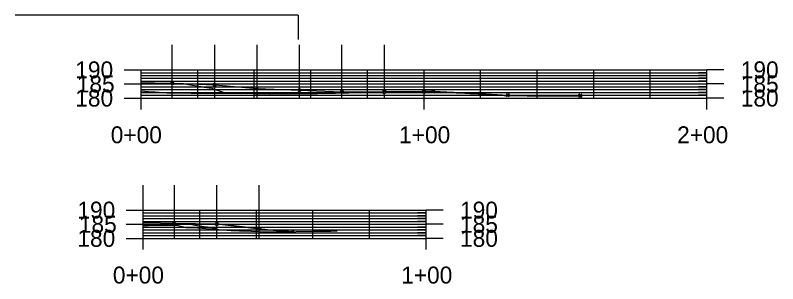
# Model space of a CAD drawing. Extents: x 1 to 1477871, y 1 to 1872901.
# Drawn here: x 1446288.5 to 1446558.1, y 1852258.5 to 1852353.6 of the extents above; entities that cross this region are included whole.
import ezdxf

# ---------------------------------------------------------------- set-up
doc = ezdxf.new("R2010")
doc.units = 0
for name, color, linetype in [('B_Concrete', 7, 'Continuous'), ('Default', 7, 'Continuous'), ('R_Axis', 7, 'Continuous'), ('R_Axis Annot', 7, 'Continuous'), ('R_Grid', 7, 'Continuous'), ('R_No Plot', 7, 'Continuous'), ('R_Point Sym', 7, 'Continuous'), ('R_Vert Alg Annot', 7, 'Continuous')]:
    doc.layers.add(name, color=color, linetype=linetype)

msp = doc.modelspace()

# ---------------------------------------------------------------- linework, layer by layer
at = {"layer": 'B_Concrete'}
msp.add_line((1446488.3, 1852324.99), (1446488.3, 1852325.56), dxfattribs=at)
at = {"layer": 'Default'}
for p, q in [((1446344.04, 1852329.55), (1446359.04, 1852328.95)), ((1446344.04, 1852329.55), (1446359.04, 1852328.95)), ((1446359.04, 1852328.95), (1446374.04, 1852327.66)), ((1446359.04, 1852328.95), (1446374.04, 1852327.66)), ((1446374.04, 1852327.66), (1446389.04, 1852327.06)), ((1446374.04, 1852327.66), (1446389.04, 1852327.06)), ((1446389.04, 1852327.06), (1446404.04, 1852326.46)), ((1446389.04, 1852327.06), (1446404.04, 1852326.46)), ((1446404.04, 1852326.46), (1446419.04, 1852326.59)), ((1446404.04, 1852326.46), (1446419.04, 1852326.41)), ((1446419.04, 1852326.59), (1446433.04, 1852326.69)), ((1446419.04, 1852326.41), (1446433.04, 1852326.54)), ((1446433.04, 1852326.69), (1446436.35, 1852326.69)), ((1446433.04, 1852326.54), (1446436.33, 1852326.57)), ((1446436.33, 1852326.57), (1446453.04, 1852325.73)), ((1446436.35, 1852326.69), (1446453.04, 1852325.87)), ((1446453.04, 1852325.87), (1446462.75, 1852325.35)), ((1446453.04, 1852325.73), (1446462.7, 1852325.18)), ((1446462.7, 1852325.18), (1446488.3, 1852324.99)), ((1446462.75, 1852325.35), (1446488.3, 1852325.21)), ((1446344.78, 1852279.98), (1446359.78, 1852279.69)), ((1446359.78, 1852279.69), (1446374.78, 1852277.96)), ((1446374.78, 1852277.96), (1446386.68, 1852276.99))]:
    msp.add_line(p, q, dxfattribs=at)
for points in [[(1446333.04, 1852329.77), (1446333.04, 1852329.77), (1446342.55, 1852329.57), (1446344.04, 1852329.55), (1446347.47, 1852329.41), (1446348.04, 1852329.39), (1446349.07, 1852329.21), (1446354.88, 1852328.24), (1446355.34, 1852328.17), (1446358.04, 1852327.72), (1446358.8, 1852327.46), (1446363.15, 1852326.01)], [(1446333.04, 1852329.77), (1446333.04, 1852329.77), (1446342.55, 1852329.57), (1446344.04, 1852329.55), (1446347.47, 1852329.41), (1446348.04, 1852329.39), (1446349.07, 1852329.21), (1446354.88, 1852328.24), (1446355.34, 1852328.17), (1446358.04, 1852327.72), (1446358.8, 1852327.46), (1446363.15, 1852326.01)], [(1446333.04, 1852326.8), (1446335.68, 1852326.62), (1446337.98, 1852326.44), (1446342.15, 1852326.08), (1446345.2, 1852326.07), (1446350.71, 1852326.01), (1446355.72, 1852325.97), (1446359, 1852326), (1446361.44, 1852326.01), (1446363.73, 1852326.02), (1446365.32, 1852326.02), (1446366.9, 1852326.03), (1446368.31, 1852326.03), (1446368.48, 1852326.03), (1446370.07, 1852325.99), (1446371.65, 1852325.96), (1446373.24, 1852325.92), (1446374.39, 1852325.9), (1446374.82, 1852325.89), (1446375.37, 1852325.88), (1446376.41, 1852325.86), (1446377.99, 1852325.83), (1446378.39, 1852325.82), (1446379.58, 1852325.83), (1446381.16, 1852325.84), (1446382.74, 1852325.85), (1446383.12, 1852325.85), (1446384.33, 1852325.85), (1446385.91, 1852325.85), (1446386.93, 1852325.85), (1446387.5, 1852325.86), (1446389.08, 1852325.88), (1446390.67, 1852325.9), (1446390.75, 1852325.9), (1446392.25, 1852325.9), (1446393.84, 1852325.9), (1446394.57, 1852325.9), (1446395.42, 1852325.92), (1446396.5, 1852325.95), (1446397, 1852325.96), (1446398.59, 1852325.99), (1446400.17, 1852326.02), (1446401.14, 1852326.04), (1446401.76, 1852326.05), (1446403.34, 1852326.09), (1446404.93, 1852326.13), (1446406.51, 1852326.17), (1446408.1, 1852326.21), (1446409.68, 1852326.25), (1446411.27, 1852326.29), (1446411.54, 1852326.3), (1446412.85, 1852326.31), (1446414.43, 1852326.33), (1446415.19, 1852326.34), (1446416.02, 1852326.36), (1446417.6, 1852326.39), (1446419.19, 1852326.41), (1446420.77, 1852326.44), (1446421.96, 1852326.46), (1446422.36, 1852326.46), (1446423.82, 1852326.44), (1446423.94, 1852326.44), (1446425.53, 1852326.49), (1446425.96, 1852326.5), (1446427.11, 1852326.5), (1446428.68, 1852326.52), (1446430.25, 1852326.53), (1446431.82, 1852326.54), (1446431.82, 1852326.54), (1446433.39, 1852326.54), (1446434.96, 1852326.55), (1446436.33, 1852326.55), (1446436.52, 1852326.54), (1446438.09, 1852326.46), (1446439.66, 1852326.38), (1446440.62, 1852326.33), (1446441.23, 1852326.3), (1446442.8, 1852326.23), (1446444.37, 1852326.16), (1446445.49, 1852326.11), (1446445.94, 1852326.09), (1446447.51, 1852326.02), (1446449.08, 1852325.95), (1446449.21, 1852325.94), (1446450.65, 1852325.86), (1446452.22, 1852325.78), (1446452.58, 1852325.77), (1446453.78, 1852325.68), (1446455.35, 1852325.58), (1446456.92, 1852325.48), (1446458.49, 1852325.38), (1446460.06, 1852325.3), (1446461.34, 1852325.23), (1446461.63, 1852325.21), (1446462.69, 1852325.13), (1446463.2, 1852325.13), (1446464.77, 1852325.13), (1446466.34, 1852325.12), (1446467.91, 1852325.12), (1446469.48, 1852325.11), (1446469.93, 1852325.11), (1446471.04, 1852325.1), (1446472.61, 1852325.1), (1446474.18, 1852325.09), (1446475.75, 1852325.08), (1446477.32, 1852325.07), (1446477.36, 1852325.07), (1446478.89, 1852325.06), (1446479.37, 1852325.06), (1446480.46, 1852325.06), (1446481.94, 1852325.05), (1446482.03, 1852325.05), (1446483.6, 1852325.03), (1446485.17, 1852325.02), (1446486.74, 1852325.01), (1446488.3, 1852324.99)], [(1446333.04, 1852326.8), (1446335.68, 1852326.62), (1446337.98, 1852326.44), (1446342.15, 1852326.08), (1446345.2, 1852326.07), (1446350.71, 1852326.01), (1446355.72, 1852325.97), (1446359, 1852326), (1446361.44, 1852326.01), (1446363.73, 1852326.02), (1446365.32, 1852326.02), (1446366.9, 1852326.03), (1446368.31, 1852326.03), (1446368.48, 1852326.03), (1446370.07, 1852325.99), (1446371.65, 1852325.96), (1446373.24, 1852325.92), (1446374.39, 1852325.9), (1446374.82, 1852325.89), (1446375.37, 1852325.88), (1446376.41, 1852325.86), (1446377.99, 1852325.83), (1446378.39, 1852325.82), (1446379.58, 1852325.83), (1446381.16, 1852325.84), (1446382.74, 1852325.85), (1446383.12, 1852325.85), (1446384.33, 1852325.85), (1446385.91, 1852325.85), (1446386.93, 1852325.85), (1446387.5, 1852325.86), (1446389.08, 1852325.88), (1446390.67, 1852325.9), (1446390.75, 1852325.9), (1446392.25, 1852325.9), (1446393.84, 1852325.9), (1446394.57, 1852325.9), (1446395.42, 1852325.92), (1446396.5, 1852325.95), (1446397, 1852325.96), (1446398.59, 1852325.99), (1446400.17, 1852326.02), (1446401.14, 1852326.04), (1446401.76, 1852326.05), (1446403.34, 1852326.09), (1446404.93, 1852326.13), (1446406.51, 1852326.17), (1446408.1, 1852326.21), (1446409.68, 1852326.25), (1446411.27, 1852326.29), (1446411.54, 1852326.3), (1446412.85, 1852326.31), (1446414.43, 1852326.33), (1446415.19, 1852326.34), (1446416.02, 1852326.36), (1446417.6, 1852326.39), (1446419.19, 1852326.41), (1446420.77, 1852326.44), (1446421.96, 1852326.46), (1446422.36, 1852326.46), (1446423.82, 1852326.44), (1446423.94, 1852326.44), (1446425.53, 1852326.49), (1446425.96, 1852326.5), (1446427.11, 1852326.5), (1446428.68, 1852326.52), (1446430.25, 1852326.53), (1446431.82, 1852326.54), (1446431.82, 1852326.54), (1446433.39, 1852326.54), (1446434.96, 1852326.55), (1446436.33, 1852326.55), (1446436.52, 1852326.54), (1446438.09, 1852326.46), (1446439.66, 1852326.38), (1446440.62, 1852326.33), (1446441.23, 1852326.3), (1446442.8, 1852326.23), (1446444.37, 1852326.16), (1446445.49, 1852326.11), (1446445.94, 1852326.09), (1446447.51, 1852326.02), (1446449.08, 1852325.95), (1446449.21, 1852325.94), (1446450.65, 1852325.86), (1446452.22, 1852325.78), (1446452.58, 1852325.77), (1446453.78, 1852325.68), (1446455.35, 1852325.58), (1446456.92, 1852325.48), (1446458.49, 1852325.38), (1446460.06, 1852325.3), (1446461.34, 1852325.23), (1446461.63, 1852325.21), (1446462.69, 1852325.13), (1446463.2, 1852325.13), (1446464.77, 1852325.13), (1446466.34, 1852325.12), (1446467.91, 1852325.12), (1446469.48, 1852325.11), (1446469.93, 1852325.11), (1446471.04, 1852325.1), (1446472.61, 1852325.1), (1446474.18, 1852325.09), (1446475.75, 1852325.08), (1446477.32, 1852325.07), (1446477.36, 1852325.07), (1446478.89, 1852325.06), (1446479.37, 1852325.06), (1446480.46, 1852325.06), (1446481.94, 1852325.05), (1446482.03, 1852325.05), (1446483.6, 1852325.03), (1446485.17, 1852325.02), (1446486.74, 1852325.01), (1446488.3, 1852324.99)], [(1446333.78, 1852280.19), (1446334.93, 1852280.17), (1446344.78, 1852279.98), (1446345.2, 1852279.97), (1446348.78, 1852279.9), (1446349.55, 1852279.77), (1446352.95, 1852279.2), (1446354.44, 1852278.96), (1446355.92, 1852278.71), (1446356.18, 1852278.66), (1446356.53, 1852278.61), (1446357.41, 1852278.46), (1446358.79, 1852278.23), (1446358.89, 1852278.2), (1446359.07, 1852278.14), (1446360.33, 1852277.73)], [(1446333.78, 1852279.13), (1446335.46, 1852279.19), (1446338.51, 1852279.26), (1446341.85, 1852279.29), (1446344.93, 1852279.25), (1446345.69, 1852279.24), (1446347.55, 1852278.79), (1446348.89, 1852278.46), (1446350.04, 1852278.39), (1446352.95, 1852278.28), (1446353.21, 1852278.28), (1446354.44, 1852278.19), (1446355.92, 1852278.09), (1446357.33, 1852278), (1446357.41, 1852277.99), (1446358.89, 1852277.86), (1446360.37, 1852277.72), (1446361.86, 1852277.59), (1446363.34, 1852277.46), (1446363.38, 1852277.46), (1446364.83, 1852277.4), (1446366.31, 1852277.34), (1446367.8, 1852277.28), (1446369.28, 1852277.22), (1446372.03, 1852277.11), (1446377.09, 1852276.87), (1446379.27, 1852276.88), (1446381.95, 1852276.9), (1446393.63, 1852277.11), (1446396.95, 1852277.17), (1446400.1, 1852277.18), (1446402.29, 1852277.2)]]:
    msp.add_lwpolyline(points, dxfattribs=at)
at = {"layer": 'R_Axis'}
for p, q in [((1446333.04, 1852324.26), (1446333.04, 1852334.26)), ((1446333.04, 1852324.26), (1446333.04, 1852334.26)), ((1446533.04, 1852324.26), (1446533.04, 1852334.26)), ((1446533.04, 1852324.26), (1446533.04, 1852334.26)), ((1446333.04, 1852324.26), (1446533.04, 1852324.26)), ((1446333.04, 1852324.26), (1446533.04, 1852324.26)), ((1446333.78, 1852274.59), (1446333.78, 1852284.59)), ((1446433.78, 1852274.59), (1446433.78, 1852284.59)), ((1446333.78, 1852274.59), (1446433.78, 1852274.59))]:
    msp.add_line(p, q, dxfattribs=at)
at = {"layer": 'R_Grid'}
for p, q in [((1446327.04, 1852334.26), (1446333.04, 1852334.26)), ((1446327.04, 1852334.26), (1446333.04, 1852334.26)), ((1446327.04, 1852334.26), (1446333.04, 1852334.26)), ((1446327.04, 1852334.26), (1446333.04, 1852334.26)), ((1446333.04, 1852334.26), (1446533.04, 1852334.26)), ((1446333.04, 1852334.26), (1446533.04, 1852334.26)), ((1446333.04, 1852334.26), (1446533.04, 1852334.26)), ((1446333.04, 1852334.26), (1446533.04, 1852334.26)), ((1446333.04, 1852333.26), (1446336.04, 1852333.26)), ((1446333.04, 1852333.26), (1446533.04, 1852333.26)), ((1446333.04, 1852333.26), (1446336.04, 1852333.26)), ((1446333.04, 1852333.26), (1446533.04, 1852333.26)), ((1446353.04, 1852324.26), (1446353.04, 1852334.26)), ((1446353.04, 1852324.26), (1446353.04, 1852334.26)), ((1446373.04, 1852324.26), (1446373.04, 1852334.26)), ((1446373.04, 1852324.26), (1446373.04, 1852334.26)), ((1446393.04, 1852324.26), (1446393.04, 1852334.26)), ((1446393.04, 1852324.26), (1446393.04, 1852334.26)), ((1446413.04, 1852324.26), (1446413.04, 1852334.26)), ((1446413.04, 1852324.26), (1446413.04, 1852334.26)), ((1446433.04, 1852324.26), (1446433.04, 1852334.26)), ((1446433.04, 1852324.26), (1446433.04, 1852334.26)), ((1446453.04, 1852324.26), (1446453.04, 1852334.26)), ((1446453.04, 1852324.26), (1446453.04, 1852334.26)), ((1446473.04, 1852324.26), (1446473.04, 1852334.26)), ((1446473.04, 1852324.26), (1446473.04, 1852334.26)), ((1446493.04, 1852324.26), (1446493.04, 1852334.26)), ((1446493.04, 1852324.26), (1446493.04, 1852334.26)), ((1446513.04, 1852324.26), (1446513.04, 1852334.26)), ((1446513.04, 1852324.26), (1446513.04, 1852334.26)), ((1446533.04, 1852333.26), (1446530.04, 1852333.26)), ((1446533.04, 1852333.26), (1446530.04, 1852333.26)), ((1446539.04, 1852334.26), (1446533.04, 1852334.26)), ((1446539.04, 1852334.26), (1446533.04, 1852334.26)), ((1446539.04, 1852334.26), (1446533.04, 1852334.26)), ((1446539.04, 1852334.26), (1446533.04, 1852334.26)), ((1446333.04, 1852332.26), (1446336.04, 1852332.26)), ((1446333.04, 1852332.26), (1446533.04, 1852332.26)), ((1446333.04, 1852332.26), (1446336.04, 1852332.26)), ((1446333.04, 1852332.26), (1446533.04, 1852332.26)), ((1446333.04, 1852331.26), (1446336.04, 1852331.26)), ((1446333.04, 1852331.26), (1446533.04, 1852331.26)), ((1446333.04, 1852331.26), (1446336.04, 1852331.26)), ((1446333.04, 1852331.26), (1446533.04, 1852331.26)), ((1446333.04, 1852330.26), (1446336.04, 1852330.26)), ((1446333.04, 1852330.26), (1446533.04, 1852330.26)), ((1446333.04, 1852330.26), (1446336.04, 1852330.26)), ((1446333.04, 1852330.26), (1446533.04, 1852330.26)), ((1446533.04, 1852332.26), (1446530.04, 1852332.26)), ((1446533.04, 1852332.26), (1446530.04, 1852332.26)), ((1446533.04, 1852331.26), (1446530.04, 1852331.26)), ((1446533.04, 1852331.26), (1446530.04, 1852331.26)), ((1446533.04, 1852330.26), (1446530.04, 1852330.26)), ((1446533.04, 1852330.26), (1446530.04, 1852330.26)), ((1446327.04, 1852329.26), (1446333.04, 1852329.26)), ((1446327.04, 1852329.26), (1446333.04, 1852329.26)), ((1446333.04, 1852329.26), (1446533.04, 1852329.26)), ((1446333.04, 1852329.26), (1446533.04, 1852329.26)), ((1446333.04, 1852328.26), (1446336.04, 1852328.26)), ((1446333.04, 1852328.26), (1446533.04, 1852328.26)), ((1446333.04, 1852328.26), (1446336.04, 1852328.26)), ((1446333.04, 1852328.26), (1446533.04, 1852328.26)), ((1446333.04, 1852327.26), (1446336.04, 1852327.26)), ((1446333.04, 1852327.26), (1446533.04, 1852327.26)), ((1446333.04, 1852327.26), (1446336.04, 1852327.26)), ((1446333.04, 1852327.26), (1446533.04, 1852327.26)), ((1446533.04, 1852328.26), (1446530.04, 1852328.26)), ((1446533.04, 1852328.26), (1446530.04, 1852328.26)), ((1446533.04, 1852327.26), (1446530.04, 1852327.26)), ((1446533.04, 1852327.26), (1446530.04, 1852327.26)), ((1446539.04, 1852329.26), (1446533.04, 1852329.26)), ((1446539.04, 1852329.26), (1446533.04, 1852329.26)), ((1446333.04, 1852326.26), (1446336.04, 1852326.26)), ((1446333.04, 1852326.26), (1446533.04, 1852326.26)), ((1446333.04, 1852326.26), (1446336.04, 1852326.26)), ((1446333.04, 1852326.26), (1446533.04, 1852326.26)), ((1446333.04, 1852325.26), (1446336.04, 1852325.26)), ((1446333.04, 1852325.26), (1446533.04, 1852325.26)), ((1446333.04, 1852325.26), (1446336.04, 1852325.26)), ((1446333.04, 1852325.26), (1446533.04, 1852325.26)), ((1446533.04, 1852326.26), (1446530.04, 1852326.26)), ((1446533.04, 1852326.26), (1446530.04, 1852326.26)), ((1446533.04, 1852325.26), (1446530.04, 1852325.26)), ((1446533.04, 1852325.26), (1446530.04, 1852325.26)), ((1446327.04, 1852324.26), (1446333.04, 1852324.26)), ((1446327.04, 1852324.26), (1446333.04, 1852324.26)), ((1446333.04, 1852320.26), (1446333.04, 1852324.26)), ((1446333.04, 1852320.26), (1446333.04, 1852324.26)), ((1446433.04, 1852320.26), (1446433.04, 1852324.26)), ((1446433.04, 1852320.26), (1446433.04, 1852324.26)), ((1446539.04, 1852324.26), (1446533.04, 1852324.26)), ((1446533.04, 1852320.26), (1446533.04, 1852324.26)), ((1446539.04, 1852324.26), (1446533.04, 1852324.26)), ((1446533.04, 1852320.26), (1446533.04, 1852324.26)), ((1446327.78, 1852284.59), (1446333.78, 1852284.59)), ((1446327.78, 1852284.59), (1446333.78, 1852284.59)), ((1446333.78, 1852284.59), (1446433.78, 1852284.59)), ((1446333.78, 1852284.59), (1446433.78, 1852284.59)), ((1446353.78, 1852274.59), (1446353.78, 1852284.59)), ((1446373.78, 1852274.59), (1446373.78, 1852284.59)), ((1446393.78, 1852274.59), (1446393.78, 1852284.59)), ((1446413.78, 1852274.59), (1446413.78, 1852284.59)), ((1446439.78, 1852284.59), (1446433.78, 1852284.59)), ((1446439.78, 1852284.59), (1446433.78, 1852284.59)), ((1446333.78, 1852283.59), (1446336.78, 1852283.59)), ((1446333.78, 1852283.59), (1446433.78, 1852283.59)), ((1446333.78, 1852282.59), (1446336.78, 1852282.59)), ((1446333.78, 1852282.59), (1446433.78, 1852282.59)), ((1446333.78, 1852281.59), (1446336.78, 1852281.59)), ((1446333.78, 1852281.59), (1446433.78, 1852281.59)), ((1446433.78, 1852283.59), (1446430.78, 1852283.59)), ((1446433.78, 1852282.59), (1446430.78, 1852282.59)), ((1446433.78, 1852281.59), (1446430.78, 1852281.59)), ((1446327.78, 1852279.59), (1446333.78, 1852279.59)), ((1446333.78, 1852280.59), (1446336.78, 1852280.59)), ((1446333.78, 1852280.59), (1446433.78, 1852280.59)), ((1446333.78, 1852279.59), (1446433.78, 1852279.59)), ((1446433.78, 1852280.59), (1446430.78, 1852280.59)), ((1446439.78, 1852279.59), (1446433.78, 1852279.59)), ((1446333.78, 1852278.59), (1446336.78, 1852278.59)), ((1446333.78, 1852278.59), (1446433.78, 1852278.59)), ((1446333.78, 1852277.59), (1446336.78, 1852277.59)), ((1446333.78, 1852277.59), (1446433.78, 1852277.59)), ((1446333.78, 1852276.59), (1446336.78, 1852276.59)), ((1446333.78, 1852276.59), (1446433.78, 1852276.59)), ((1446433.78, 1852278.59), (1446430.78, 1852278.59)), ((1446433.78, 1852277.59), (1446430.78, 1852277.59)), ((1446433.78, 1852276.59), (1446430.78, 1852276.59)), ((1446327.78, 1852274.59), (1446333.78, 1852274.59)), ((1446333.78, 1852275.59), (1446336.78, 1852275.59)), ((1446333.78, 1852275.59), (1446433.78, 1852275.59)), ((1446333.78, 1852270.59), (1446333.78, 1852274.59)), ((1446433.78, 1852275.59), (1446430.78, 1852275.59)), ((1446439.78, 1852274.59), (1446433.78, 1852274.59)), ((1446433.78, 1852270.59), (1446433.78, 1852274.59))]:
    msp.add_line(p, q, dxfattribs=at)
at = {"layer": 'R_No Plot'}
for p, q in [((1446388.52, 1852353.6), (1446288.52, 1852353.6)), ((1446388.52, 1852353.6), (1446388.52, 1852345)), ((1446344.04, 1852324.26), (1446344.04, 1852343.14)), ((1446344.04, 1852324.26), (1446344.04, 1852343.14)), ((1446359.04, 1852324.26), (1446359.04, 1852343.14)), ((1446374.04, 1852324.26), (1446374.04, 1852343.14)), ((1446389.04, 1852324.26), (1446389.04, 1852343.14)), ((1446404.04, 1852324.26), (1446404.04, 1852343.14)), ((1446419.04, 1852324.26), (1446419.04, 1852343.14)), ((1446344.04, 1852329.55), (1446359.04, 1852328.95)), ((1446359.04, 1852328.95), (1446374.04, 1852327.66)), ((1446374.04, 1852327.66), (1446404.04, 1852326.46)), ((1446404.04, 1852326.46), (1446419.04, 1852326.41)), ((1446419.04, 1852326.41), (1446436.33, 1852326.57)), ((1446333.78, 1852274.59), (1446333.78, 1852293.47)), ((1446344.78, 1852274.59), (1446344.78, 1852293.47)), ((1446344.78, 1852274.59), (1446344.78, 1852293.47)), ((1446359.78, 1852274.59), (1446359.78, 1852293.47)), ((1446374.78, 1852274.59), (1446374.78, 1852293.47)), ((1446344.78, 1852279.98), (1446359.78, 1852279.69)), ((1446383.69, 1852276.94), (1446359.78, 1852279.69)), ((1446374.78, 1852277.96), (1446386.68, 1852276.99))]:
    msp.add_line(p, q, dxfattribs=at)
at = {"layer": 'R_Point Sym'}
for points in [[(1446344.04, 1852329.55), (1446343.54, 1852330.05), (1446344.04, 1852329.55), (1446343.54, 1852329.05), (1446344.04, 1852329.55), (1446344.54, 1852329.05), (1446344.04, 1852329.55), (1446344.54, 1852330.05)], [(1446344.04, 1852329.55), (1446343.54, 1852330.05), (1446344.04, 1852329.55), (1446343.54, 1852329.05), (1446344.04, 1852329.55), (1446344.54, 1852329.05), (1446344.04, 1852329.55), (1446344.54, 1852330.05)], [(1446359.04, 1852328.95), (1446358.54, 1852329.45), (1446359.04, 1852328.95), (1446358.54, 1852328.45), (1446359.04, 1852328.95), (1446359.54, 1852328.45), (1446359.04, 1852328.95), (1446359.54, 1852329.45)], [(1446359.04, 1852328.95), (1446358.54, 1852329.45), (1446359.04, 1852328.95), (1446358.54, 1852328.45), (1446359.04, 1852328.95), (1446359.54, 1852328.45), (1446359.04, 1852328.95), (1446359.54, 1852329.45)], [(1446374.04, 1852327.66), (1446373.54, 1852328.16), (1446374.04, 1852327.66), (1446373.54, 1852327.16), (1446374.04, 1852327.66), (1446374.54, 1852327.16), (1446374.04, 1852327.66), (1446374.54, 1852328.16)], [(1446374.04, 1852327.66), (1446373.54, 1852328.16), (1446374.04, 1852327.66), (1446373.54, 1852327.16), (1446374.04, 1852327.66), (1446374.54, 1852327.16), (1446374.04, 1852327.66), (1446374.54, 1852328.16)], [(1446389.04, 1852327.06), (1446388.54, 1852327.56), (1446389.04, 1852327.06), (1446388.54, 1852326.56), (1446389.04, 1852327.06), (1446389.54, 1852326.56), (1446389.04, 1852327.06), (1446389.54, 1852327.56)], [(1446389.04, 1852327.06), (1446388.54, 1852327.56), (1446389.04, 1852327.06), (1446388.54, 1852326.56), (1446389.04, 1852327.06), (1446389.54, 1852326.56), (1446389.04, 1852327.06), (1446389.54, 1852327.56)], [(1446433.04, 1852326.69), (1446432.54, 1852327.19), (1446433.04, 1852326.69), (1446432.54, 1852326.19), (1446433.04, 1852326.69), (1446433.54, 1852326.19), (1446433.04, 1852326.69), (1446433.54, 1852327.19)], [(1446436.35, 1852326.69), (1446435.85, 1852327.19), (1446436.35, 1852326.69), (1446435.85, 1852326.19), (1446436.35, 1852326.69), (1446436.85, 1852326.19), (1446436.35, 1852326.69), (1446436.85, 1852327.19)], [(1446404.04, 1852326.46), (1446403.54, 1852326.96), (1446404.04, 1852326.46), (1446403.54, 1852325.96), (1446404.04, 1852326.46), (1446404.54, 1852325.96), (1446404.04, 1852326.46), (1446404.54, 1852326.96)], [(1446404.04, 1852326.46), (1446403.54, 1852326.96), (1446404.04, 1852326.46), (1446403.54, 1852325.96), (1446404.04, 1852326.46), (1446404.54, 1852325.96), (1446404.04, 1852326.46), (1446404.54, 1852326.96)], [(1446419.04, 1852326.59), (1446418.54, 1852327.09), (1446419.04, 1852326.59), (1446418.54, 1852326.09), (1446419.04, 1852326.59), (1446419.54, 1852326.09), (1446419.04, 1852326.59), (1446419.54, 1852327.09)], [(1446419.04, 1852326.41), (1446418.54, 1852326.91), (1446419.04, 1852326.41), (1446418.54, 1852325.91), (1446419.04, 1852326.41), (1446419.54, 1852325.91), (1446419.04, 1852326.41), (1446419.54, 1852326.91)], [(1446433.04, 1852326.54), (1446432.54, 1852327.04), (1446433.04, 1852326.54), (1446432.54, 1852326.04), (1446433.04, 1852326.54), (1446433.54, 1852326.04), (1446433.04, 1852326.54), (1446433.54, 1852327.04)], [(1446436.33, 1852326.57), (1446435.83, 1852327.07), (1446436.33, 1852326.57), (1446435.83, 1852326.07), (1446436.33, 1852326.57), (1446436.83, 1852326.07), (1446436.33, 1852326.57), (1446436.83, 1852327.07)], [(1446453.04, 1852325.87), (1446452.54, 1852326.37), (1446453.04, 1852325.87), (1446452.54, 1852325.37), (1446453.04, 1852325.87), (1446453.54, 1852325.37), (1446453.04, 1852325.87), (1446453.54, 1852326.37)], [(1446453.04, 1852325.73), (1446452.54, 1852326.23), (1446453.04, 1852325.73), (1446452.54, 1852325.23), (1446453.04, 1852325.73), (1446453.54, 1852325.23), (1446453.04, 1852325.73), (1446453.54, 1852326.23)], [(1446462.7, 1852325.18), (1446462.2, 1852325.68), (1446462.7, 1852325.18), (1446462.2, 1852324.68), (1446462.7, 1852325.18), (1446463.2, 1852324.68), (1446462.7, 1852325.18), (1446463.2, 1852325.68)], [(1446462.75, 1852325.35), (1446462.25, 1852325.85), (1446462.75, 1852325.35), (1446462.25, 1852324.85), (1446462.75, 1852325.35), (1446463.25, 1852324.85), (1446462.75, 1852325.35), (1446463.25, 1852325.85)], [(1446488.3, 1852325.21), (1446487.8, 1852325.71), (1446488.3, 1852325.21), (1446487.8, 1852324.71), (1446488.3, 1852325.21), (1446488.8, 1852324.71), (1446488.3, 1852325.21), (1446488.8, 1852325.71)], [(1446488.3, 1852324.99), (1446487.8, 1852325.49), (1446488.3, 1852324.99), (1446487.8, 1852324.49), (1446488.3, 1852324.99), (1446488.8, 1852324.49), (1446488.3, 1852324.99), (1446488.8, 1852325.49)], [(1446344.78, 1852279.98), (1446344.28, 1852280.48), (1446344.78, 1852279.98), (1446344.28, 1852279.48), (1446344.78, 1852279.98), (1446345.28, 1852279.48), (1446344.78, 1852279.98), (1446345.28, 1852280.48)], [(1446359.78, 1852279.69), (1446359.28, 1852280.19), (1446359.78, 1852279.69), (1446359.28, 1852279.19), (1446359.78, 1852279.69), (1446360.28, 1852279.19), (1446359.78, 1852279.69), (1446360.28, 1852280.19)], [(1446374.78, 1852277.96), (1446374.28, 1852278.46), (1446374.78, 1852277.96), (1446374.28, 1852277.46), (1446374.78, 1852277.96), (1446375.28, 1852277.46), (1446374.78, 1852277.96), (1446375.28, 1852278.46)], [(1446386.68, 1852276.99), (1446386.18, 1852277.49), (1446386.68, 1852276.99), (1446386.18, 1852276.49), (1446386.68, 1852276.99), (1446387.18, 1852276.49), (1446386.68, 1852276.99), (1446387.18, 1852277.49)]]:
    msp.add_lwpolyline(points, dxfattribs=at)

# ---------------------------------------------------------------- texts
at = {"layer": 'R_Axis'}
for s, p in [('190', (1446309.75, 1852331.26)), ('190', (1446309.75, 1852331.26)), ('190', (1446309.75, 1852331.26)), ('190', (1446309.75, 1852331.26)), ('185', (1446310.27, 1852326.26)), ('185', (1446310.27, 1852326.26)), ('180', (1446309.75, 1852321.26)), ('180', (1446309.75, 1852321.26)), ('190', (1446310.49, 1852281.59)), ('190', (1446310.49, 1852281.59)), ('185', (1446311.01, 1852276.59)), ('180', (1446310.49, 1852271.59))]:
    msp.add_text(s, height=6, dxfattribs=at).set_placement(p)
at = {"layer": 'R_Axis Annot'}
for s, height, p in [('190', 6, (1446545.04, 1852331.26)), ('190', 6, (1446545.04, 1852331.26)), ('190', 6, (1446545.04, 1852331.26)), ('190', 6, (1446545.04, 1852331.26)), ('185', 6, (1446545.04, 1852326.26)), ('185', 6, (1446545.04, 1852326.26)), ('180', 6, (1446545.04, 1852321.26)), ('180', 6, (1446545.04, 1852321.26)), ('-', 0.0001, (1446333.04, 1852324.26)), ('-', 0.0001, (1446333.04, 1852324.26)), ('190', 6, (1446445.78, 1852281.59)), ('190', 6, (1446445.78, 1852281.59)), ('185', 6, (1446445.78, 1852276.59)), ('180', 6, (1446445.78, 1852271.59)), ('-', 0.0001, (1446333.78, 1852274.59))]:
    msp.add_text(s, height=height, dxfattribs=at).set_placement(p)
at = {"layer": 'R_Vert Alg Annot'}
for s, p in [('0+00', (1446322.29, 1852308.26)), ('0+00', (1446322.29, 1852308.26)), ('1+00', (1446424.23, 1852308.26)), ('1+00', (1446424.23, 1852308.26)), ('2+00', (1446522.53, 1852308.26)), ('2+00', (1446522.53, 1852308.26)), ('0+00', (1446323.03, 1852258.59)), ('1+00', (1446424.97, 1852258.59))]:
    msp.add_text(s, height=6, dxfattribs=at).set_placement(p)

doc.saveas('drawing.dxf')
